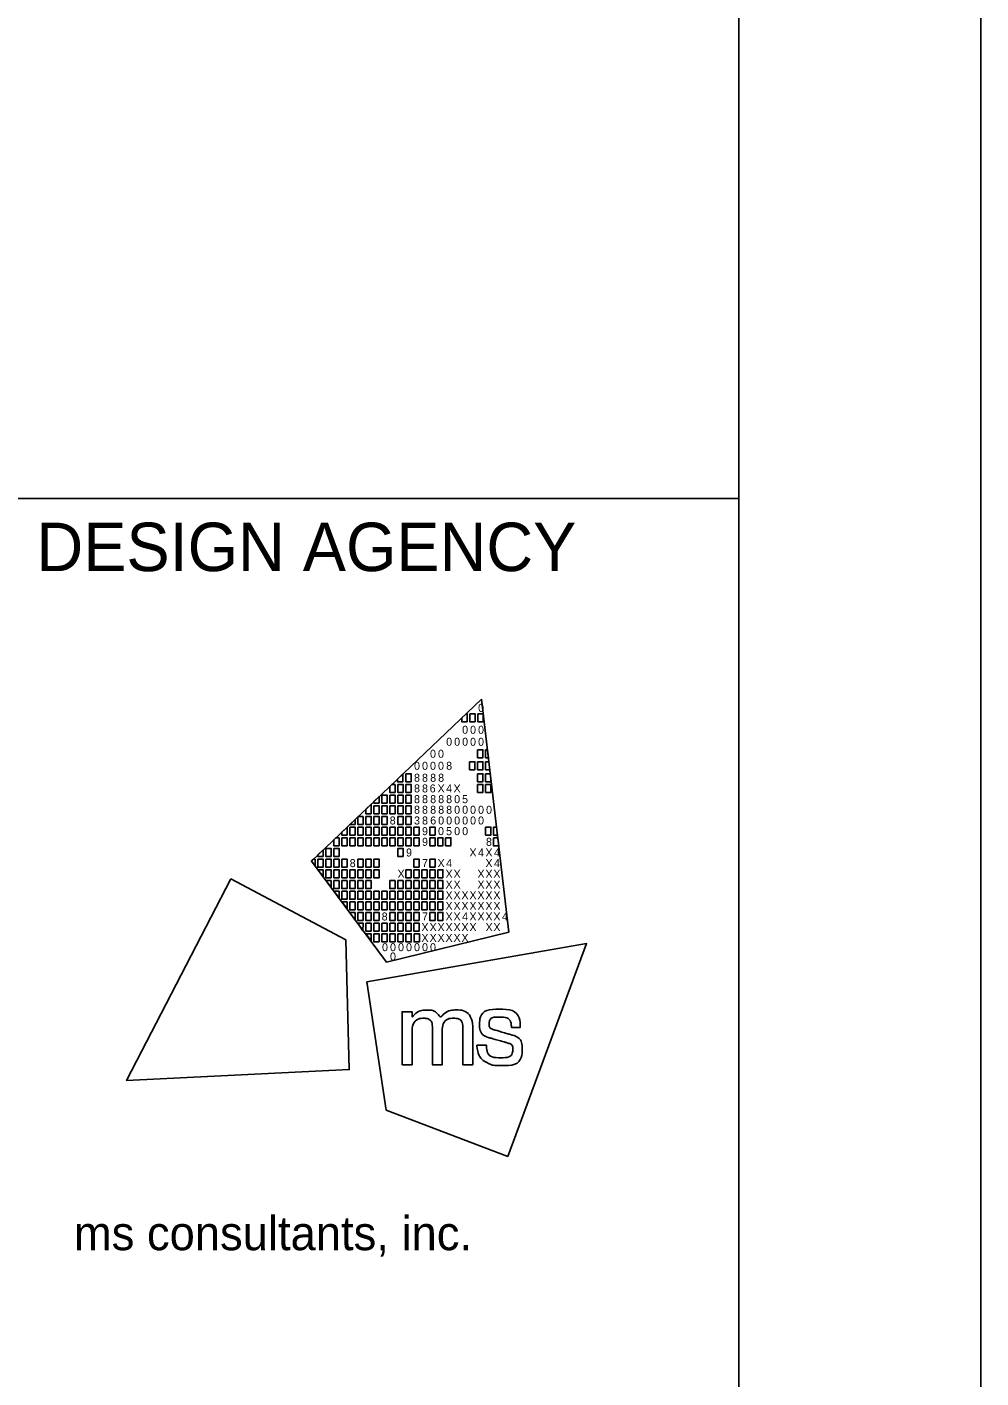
# Model space of a CAD drawing. Extents: x 0 to 34, y 0 to 22.
# Drawn here: x 32.03 to 34, y 2.685 to 5.473 of the extents above; entities that cross this region are included whole.
import ezdxf

# ---------------------------------------------------------------- set-up
doc = ezdxf.new("R2010")
doc.units = 0
for name, color, linetype in [('SH_Border', 7, 'Continuous'), ('SH_Cut_Line', 7, 'Continuous'), ('SH_Data', 7, 'Continuous'), ('SH_Text', 7, 'Continuous')]:
    doc.layers.add(name, color=color, linetype=linetype)

msp = doc.modelspace()

# ---------------------------------------------------------------- linework, layer by layer
at = {"layer": 'SH_Border'}
msp.add_line((32, 4.5), (33.5, 4.5), dxfattribs=at)
msp.add_lwpolyline([(1.5, 21.5), (33.5, 21.5), (33.5, 0.5), (1.5, 0.5)], close=True, dxfattribs=at)
at = {"layer": 'SH_Cut_Line'}
msp.add_lwpolyline([(0, 0), (34, 0), (34, 22), (0, 22)], close=True, dxfattribs=at)
at = {"layer": 'SH_Data'}
msp.add_line((32.75, 3.5), (32.75, 3.5), dxfattribs=at)
at = {"layer": 'SH_Text'}
for p, q in [((32.6175, 3.7519), (32.9688, 4.0861)), ((32.9688, 4.0861), (32.9688, 4.0861)), ((32.9688, 4.0861), (33.0253, 3.6052)), ((32.773, 3.543), (32.6175, 3.7519)), ((33.0253, 3.6052), (32.773, 3.543))]:
    msp.add_line(p, q, dxfattribs=at)
for points in [[(32.9279, 4.0472), (32.9369, 4.0558), (32.9389, 4.0558), (32.9389, 4.0393), (32.9279, 4.0393)], [(32.9444, 4.0558), (32.9554, 4.0558), (32.9554, 4.0393), (32.9444, 4.0393)], [(32.9609, 4.0558), (32.9719, 4.0558), (32.9719, 4.0393), (32.9609, 4.0393)], [(32.9606, 3.9815), (32.9716, 3.9815), (32.9716, 3.965), (32.9606, 3.965)], [(32.9771, 3.9815), (32.9811, 3.9815), (32.983, 3.965), (32.9771, 3.965)], [(32.7953, 3.9211), (32.8064, 3.9316), (32.8064, 3.9154), (32.7953, 3.9154)], [(32.8123, 3.9319), (32.8233, 3.9319), (32.8233, 3.9154), (32.8123, 3.9154)], [(32.9441, 3.9567), (32.9551, 3.9567), (32.9551, 3.9402), (32.9441, 3.9402)], [(32.9606, 3.9567), (32.9716, 3.9567), (32.9716, 3.9402), (32.9606, 3.9402)], [(32.9606, 3.9319), (32.9716, 3.9319), (32.9716, 3.9154), (32.9606, 3.9154)], [(32.9771, 3.9567), (32.984, 3.9567), (32.9859, 3.9402), (32.9771, 3.9402)], [(32.9771, 3.9319), (32.9869, 3.9319), (32.9881, 3.9218), (32.9881, 3.9154), (32.9771, 3.9154)], [(32.7958, 3.9099), (32.8068, 3.9099), (32.8068, 3.8934), (32.7958, 3.8934)], [(32.8123, 3.9099), (32.8233, 3.9099), (32.8233, 3.8934), (32.8123, 3.8934)], [(32.9606, 3.9099), (32.9716, 3.9099), (32.9716, 3.8934), (32.9606, 3.8934)], [(32.9771, 3.9099), (32.9881, 3.9099), (32.9881, 3.8934), (32.9771, 3.8934)], [(32.7627, 3.8879), (32.7737, 3.8879), (32.7737, 3.8714), (32.7627, 3.8714)], [(32.7793, 3.8879), (32.7903, 3.8879), (32.7903, 3.8714), (32.7793, 3.8714)], [(32.7958, 3.8879), (32.8068, 3.8879), (32.8068, 3.8714), (32.7958, 3.8714)], [(32.8123, 3.8879), (32.8233, 3.8879), (32.8233, 3.8714), (32.8123, 3.8714)], [(32.7462, 3.8659), (32.7572, 3.8659), (32.7572, 3.8494), (32.7462, 3.8494)], [(32.7627, 3.8659), (32.7737, 3.8659), (32.7737, 3.8494), (32.7627, 3.8494)], [(32.7793, 3.8659), (32.7903, 3.8659), (32.7903, 3.8494), (32.7793, 3.8494)], [(32.7958, 3.8659), (32.8068, 3.8659), (32.8068, 3.8494), (32.7958, 3.8494)], [(32.8123, 3.8659), (32.8233, 3.8659), (32.8233, 3.8494), (32.8123, 3.8494)], [(32.6967, 3.8218), (32.7077, 3.8218), (32.7077, 3.8053), (32.6967, 3.8053)], [(32.7132, 3.8218), (32.7242, 3.8218), (32.7242, 3.8053), (32.7132, 3.8053)], [(32.7297, 3.8439), (32.7407, 3.8439), (32.7407, 3.8273), (32.7297, 3.8273)], [(32.7297, 3.8218), (32.7407, 3.8218), (32.7407, 3.8053), (32.7297, 3.8053)], [(32.7462, 3.8439), (32.7572, 3.8439), (32.7572, 3.8273), (32.7462, 3.8273)], [(32.7462, 3.8218), (32.7572, 3.8218), (32.7572, 3.8053), (32.7462, 3.8053)], [(32.7627, 3.8439), (32.7737, 3.8439), (32.7737, 3.8273), (32.7627, 3.8273)], [(32.7627, 3.8218), (32.7737, 3.8218), (32.7737, 3.8053), (32.7627, 3.8053)], [(32.7793, 3.8218), (32.7903, 3.8218), (32.7903, 3.8053), (32.7793, 3.8053)], [(32.7958, 3.8439), (32.8068, 3.8439), (32.8068, 3.8273), (32.7958, 3.8273)], [(32.7958, 3.8218), (32.8068, 3.8218), (32.8068, 3.8053), (32.7958, 3.8053)], [(32.8123, 3.8439), (32.8233, 3.8439), (32.8233, 3.8273), (32.8123, 3.8273)], [(32.8123, 3.8218), (32.8233, 3.8218), (32.8233, 3.8053), (32.8123, 3.8053)], [(32.8288, 3.8218), (32.8398, 3.8218), (32.8398, 3.8053), (32.8288, 3.8053)], [(32.8618, 3.8218), (32.8728, 3.8218), (32.8728, 3.8053), (32.8618, 3.8053)], [(32.9771, 3.8218), (32.9881, 3.8218), (32.9881, 3.8053), (32.9771, 3.8053)], [(32.9935, 3.8218), (32.9998, 3.8218), (33.0018, 3.8053), (32.9935, 3.8053)], [(32.6802, 3.7998), (32.6912, 3.7998), (32.6912, 3.7833), (32.6802, 3.7833)], [(32.6967, 3.7998), (32.7077, 3.7998), (32.7077, 3.7833), (32.6967, 3.7833)], [(32.7132, 3.7998), (32.7242, 3.7998), (32.7242, 3.7833), (32.7132, 3.7833)], [(32.7297, 3.7998), (32.7407, 3.7998), (32.7407, 3.7833), (32.7297, 3.7833)], [(32.7462, 3.7998), (32.7572, 3.7998), (32.7572, 3.7833), (32.7462, 3.7833)], [(32.7627, 3.7998), (32.7737, 3.7998), (32.7737, 3.7833), (32.7627, 3.7833)], [(32.7793, 3.7998), (32.7903, 3.7998), (32.7903, 3.7833), (32.7793, 3.7833)], [(32.7958, 3.7998), (32.8068, 3.7998), (32.8068, 3.7833), (32.7958, 3.7833)], [(32.8123, 3.7998), (32.8233, 3.7998), (32.8233, 3.7833), (32.8123, 3.7833)], [(32.8288, 3.7998), (32.8398, 3.7998), (32.8398, 3.7833), (32.8288, 3.7833)], [(32.8618, 3.7998), (32.8728, 3.7998), (32.8728, 3.7833), (32.8618, 3.7833)], [(32.8783, 3.7998), (32.8893, 3.7998), (32.8893, 3.7833), (32.8783, 3.7833)], [(32.8947, 3.7998), (32.9057, 3.7998), (32.9057, 3.7833), (32.8947, 3.7833)], [(32.9935, 3.7998), (33.0024, 3.7998), (33.0044, 3.7833), (32.9935, 3.7833)], [(32.6471, 3.7778), (32.6581, 3.7778), (32.6581, 3.7613), (32.6471, 3.7613)], [(32.6637, 3.7778), (32.6747, 3.7778), (32.6747, 3.7613), (32.6637, 3.7613)], [(32.7958, 3.7778), (32.8068, 3.7778), (32.8068, 3.7613), (32.7958, 3.7613)], [(32.6306, 3.7558), (32.6416, 3.7558), (32.6416, 3.7393), (32.6306, 3.7393)], [(32.6471, 3.7558), (32.6581, 3.7558), (32.6581, 3.7393), (32.6471, 3.7393)], [(32.6637, 3.7558), (32.6747, 3.7558), (32.6747, 3.7393), (32.6637, 3.7393)], [(32.6802, 3.7558), (32.6912, 3.7558), (32.6912, 3.7393), (32.6802, 3.7393)], [(32.7132, 3.7558), (32.7242, 3.7558), (32.7242, 3.7393), (32.7132, 3.7393)], [(32.7297, 3.7558), (32.7407, 3.7558), (32.7407, 3.7393), (32.7297, 3.7393)], [(32.7462, 3.7558), (32.7572, 3.7558), (32.7572, 3.7393), (32.7462, 3.7393)], [(32.8288, 3.7558), (32.8398, 3.7558), (32.8398, 3.7393), (32.8288, 3.7393)], [(32.8618, 3.7558), (32.8728, 3.7558), (32.8728, 3.7393), (32.8618, 3.7393)], [(32.6306, 3.7338), (32.6416, 3.7338), (32.6416, 3.72)], [(32.6471, 3.7338), (32.6581, 3.7338), (32.6581, 3.7173), (32.6471, 3.7173)], [(32.6471, 3.7117), (32.6581, 3.7117), (32.6581, 3.698)], [(32.6637, 3.7338), (32.6747, 3.7338), (32.6747, 3.7173), (32.6637, 3.7173)], [(32.6637, 3.7117), (32.6747, 3.7117), (32.6747, 3.6952), (32.6637, 3.6952)], [(32.6802, 3.7338), (32.6912, 3.7338), (32.6912, 3.7173), (32.6802, 3.7173)], [(32.6802, 3.7117), (32.6912, 3.7117), (32.6912, 3.6952), (32.6802, 3.6952)], [(32.6967, 3.7338), (32.7077, 3.7338), (32.7077, 3.7173), (32.6967, 3.7173)], [(32.6967, 3.7117), (32.7077, 3.7117), (32.7077, 3.6952), (32.6967, 3.6952)], [(32.7132, 3.7338), (32.7242, 3.7338), (32.7242, 3.7173), (32.7132, 3.7173)], [(32.7132, 3.7117), (32.7242, 3.7117), (32.7242, 3.6952), (32.7132, 3.6952)], [(32.7297, 3.7338), (32.7407, 3.7338), (32.7407, 3.7173), (32.7297, 3.7173)], [(32.7297, 3.7117), (32.7407, 3.7117), (32.7407, 3.6952), (32.7297, 3.6952)], [(32.7462, 3.7338), (32.7572, 3.7338), (32.7572, 3.7173), (32.7462, 3.7173)], [(32.7793, 3.7117), (32.7903, 3.7117), (32.7903, 3.6952), (32.7793, 3.6952)], [(32.7958, 3.7117), (32.8068, 3.7117), (32.8068, 3.6952), (32.7958, 3.6952)], [(32.8123, 3.7338), (32.8233, 3.7338), (32.8233, 3.7173), (32.8123, 3.7173)], [(32.8123, 3.7117), (32.8233, 3.7117), (32.8233, 3.6952), (32.8123, 3.6952)], [(32.8288, 3.7338), (32.8398, 3.7338), (32.8398, 3.7173), (32.8288, 3.7173)], [(32.8288, 3.7117), (32.8398, 3.7117), (32.8398, 3.6952), (32.8288, 3.6952)], [(32.8453, 3.7338), (32.8563, 3.7338), (32.8563, 3.7173), (32.8453, 3.7173)], [(32.8453, 3.7117), (32.8563, 3.7117), (32.8563, 3.6952), (32.8453, 3.6952)], [(32.8618, 3.7338), (32.8728, 3.7338), (32.8728, 3.7173), (32.8618, 3.7173)], [(32.8618, 3.7117), (32.8728, 3.7117), (32.8728, 3.6952), (32.8618, 3.6952)], [(32.8783, 3.7338), (32.8893, 3.7338), (32.8893, 3.7173), (32.8783, 3.7173)], [(32.8783, 3.7117), (32.8893, 3.7117), (32.8893, 3.6952), (32.8783, 3.6952)], [(32.6637, 3.6897), (32.6747, 3.6897), (32.6747, 3.676)], [(32.6747, 3.6897), (32.6747, 3.6897), (32.6747, 3.6897)], [(32.6802, 3.6897), (32.6912, 3.6897), (32.6912, 3.6732), (32.6802, 3.6732)], [(32.6967, 3.6897), (32.7077, 3.6897), (32.7077, 3.6732), (32.6967, 3.6732)], [(32.7132, 3.6897), (32.7242, 3.6897), (32.7242, 3.6732), (32.7132, 3.6732)], [(32.7297, 3.6897), (32.7407, 3.6897), (32.7407, 3.6732), (32.7297, 3.6732)], [(32.7462, 3.6897), (32.7572, 3.6897), (32.7572, 3.6732), (32.7462, 3.6732)], [(32.7627, 3.6897), (32.7737, 3.6897), (32.7737, 3.6732), (32.7627, 3.6732)], [(32.7793, 3.6897), (32.7903, 3.6897), (32.7903, 3.6732), (32.7793, 3.6732)], [(32.7958, 3.6897), (32.8068, 3.6897), (32.8068, 3.6732), (32.7958, 3.6732)], [(32.8123, 3.6897), (32.8233, 3.6897), (32.8233, 3.6732), (32.8123, 3.6732)], [(32.8288, 3.6897), (32.8398, 3.6897), (32.8398, 3.6732), (32.8288, 3.6732)], [(32.8453, 3.6897), (32.8563, 3.6897), (32.8563, 3.6732), (32.8453, 3.6732)], [(32.8618, 3.6897), (32.8728, 3.6897), (32.8728, 3.6732), (32.8618, 3.6732)], [(32.8783, 3.6897), (32.8893, 3.6897), (32.8893, 3.6732), (32.8783, 3.6732)], [(32.6802, 3.6677), (32.6912, 3.6677), (32.6912, 3.654)], [(32.6967, 3.6677), (32.7077, 3.6677), (32.7077, 3.6512), (32.6967, 3.6512)], [(32.7132, 3.6677), (32.7242, 3.6677), (32.7242, 3.6512), (32.7132, 3.6512)], [(32.7297, 3.6677), (32.7407, 3.6677), (32.7407, 3.6512), (32.7297, 3.6512)], [(32.7462, 3.6677), (32.7572, 3.6677), (32.7572, 3.6512), (32.7462, 3.6512)], [(32.7627, 3.6677), (32.7737, 3.6677), (32.7737, 3.6512), (32.7627, 3.6512)], [(32.7793, 3.6677), (32.7903, 3.6677), (32.7903, 3.6512), (32.7793, 3.6512)], [(32.7958, 3.6677), (32.8068, 3.6677), (32.8068, 3.6512), (32.7958, 3.6512)], [(32.8123, 3.6677), (32.8233, 3.6677), (32.8233, 3.6512), (32.8123, 3.6512)], [(32.8288, 3.6677), (32.8398, 3.6677), (32.8398, 3.6512), (32.8288, 3.6512)], [(32.8453, 3.6677), (32.8563, 3.6677), (32.8563, 3.6512), (32.8453, 3.6512)], [(32.8618, 3.6677), (32.8728, 3.6677), (32.8728, 3.6512), (32.8618, 3.6512)], [(32.8783, 3.6677), (32.8893, 3.6677), (32.8893, 3.6512), (32.8783, 3.6512)], [(32.7077, 3.6305), (32.6965, 3.6457), (32.7077, 3.6457)], [(32.7132, 3.6457), (32.7242, 3.6457), (32.7242, 3.6292), (32.7132, 3.6292)], [(32.724, 3.6082), (32.7132, 3.6237), (32.7242, 3.6237)], [(32.7297, 3.6457), (32.7407, 3.6457), (32.7407, 3.6292), (32.7297, 3.6292)], [(32.7462, 3.6457), (32.7572, 3.6457), (32.7572, 3.6292), (32.7462, 3.6292)], [(32.7793, 3.6457), (32.7903, 3.6457), (32.7903, 3.6292), (32.7793, 3.6292)], [(32.7958, 3.6457), (32.8068, 3.6457), (32.8068, 3.6292), (32.7958, 3.6292)], [(32.8123, 3.6457), (32.8233, 3.6457), (32.8233, 3.6292), (32.8123, 3.6292)], [(32.8288, 3.6457), (32.8398, 3.6457), (32.8398, 3.6292), (32.8288, 3.6292)], [(32.8618, 3.6457), (32.8728, 3.6457), (32.8728, 3.6292), (32.8618, 3.6292)], [(32.8783, 3.6457), (32.8893, 3.6457), (32.8893, 3.6292), (32.8783, 3.6292)], [(32.7297, 3.6237), (32.7407, 3.6237), (32.7407, 3.6072), (32.7297, 3.6072)], [(32.7302, 3.6017), (32.7407, 3.6017), (32.7408, 3.5875)], [(32.7462, 3.6237), (32.7572, 3.6237), (32.7572, 3.6072), (32.7462, 3.6072)], [(32.7463, 3.6017), (32.7573, 3.6017), (32.7573, 3.5852), (32.7463, 3.5852)], [(32.7627, 3.6237), (32.7737, 3.6237), (32.7737, 3.6072), (32.7627, 3.6072)], [(32.763, 3.6017), (32.774, 3.6017), (32.774, 3.5852), (32.763, 3.5852)], [(32.7793, 3.6237), (32.7903, 3.6237), (32.7903, 3.6072), (32.7793, 3.6072)], [(32.7794, 3.6017), (32.7904, 3.6017), (32.7904, 3.5852), (32.7794, 3.5852)], [(32.7958, 3.6237), (32.8068, 3.6237), (32.8068, 3.6072), (32.7958, 3.6072)], [(32.796, 3.6017), (32.807, 3.6017), (32.807, 3.5852), (32.796, 3.5852)], [(32.8123, 3.6237), (32.8233, 3.6237), (32.8233, 3.6072), (32.8123, 3.6072)], [(32.8129, 3.6017), (32.8239, 3.6017), (32.8239, 3.5851), (32.8129, 3.5851)], [(32.8288, 3.6237), (32.8398, 3.6237), (32.8398, 3.6072), (32.8288, 3.6072)], [(32.8296, 3.6017), (32.8406, 3.6017), (32.8406, 3.5851), (32.8296, 3.5851)]]:
    msp.add_lwpolyline(points, close=True, dxfattribs=at)
for points in [[(32.7903, 3.9099), (32.7836, 3.9099), (32.7793, 3.9058), (32.7793, 3.8934), (32.7903, 3.8934), (32.7903, 3.9099)], [(32.7572, 3.8849), (32.7462, 3.8744), (32.7462, 3.8714), (32.7572, 3.8714), (32.7572, 3.8849)], [(32.7407, 3.8691), (32.7297, 3.8587), (32.7297, 3.8494), (32.7407, 3.8494), (32.7407, 3.8691)], [(32.6912, 3.822), (32.6802, 3.8115), (32.6802, 3.8053), (32.6912, 3.8053), (32.6912, 3.822)], [(32.7077, 3.8377), (32.6968, 3.8273), (32.7077, 3.8273), (32.7077, 3.8377)], [(32.7242, 3.8439), (32.7141, 3.8439), (32.7132, 3.843), (32.7132, 3.8273), (32.7242, 3.8273), (32.7242, 3.8439)], [(32.6747, 3.7998), (32.6679, 3.7998), (32.6637, 3.7958), (32.6637, 3.7833), (32.6747, 3.7833), (32.6747, 3.7998)], [(32.6416, 3.7749), (32.6306, 3.7644), (32.6306, 3.7613), (32.6416, 3.7613), (32.6416, 3.7749)], [(32.6251, 3.7558), (32.6216, 3.7558), (32.6175, 3.7519), (32.6251, 3.7417), (32.6251, 3.7558)], [(32.4512, 3.7149), (32.2359, 3.2988), (32.6956, 3.3215), (32.6884, 3.5892), (32.4512, 3.7149)], [(33.0229, 3.1422), (33.1859, 3.5814), (32.7324, 3.5029), (32.7722, 3.2381), (33.0229, 3.1422)]]:
    msp.add_lwpolyline(points, dxfattribs=at)
for points in [[(32.8048, 3.3315), (32.8048, 3.3315), (32.8048, 3.4409), (32.8048, 3.4409), (32.8048, 3.4409), (32.8255, 3.4409), (32.8255, 3.4409), (32.8255, 3.4409), (32.8255, 3.4297), (32.8255, 3.4297), (32.8346, 3.4399), (32.8457, 3.4445), (32.8555, 3.4445), (32.8688, 3.4445), (32.8791, 3.4372), (32.8837, 3.4266), (32.8915, 3.4381), (32.905, 3.4446), (32.9166, 3.4446), (32.9325, 3.4446), (32.9451, 3.435), (32.9494, 3.4213), (32.9494, 3.4212), (32.9494, 3.4212), (32.9494, 3.4212), (32.9501, 3.419), (32.9506, 3.4172), (32.9506, 3.4071), (32.9506, 3.4071), (32.9506, 3.3314), (32.9506, 3.3314), (32.9506, 3.3314), (32.9303, 3.3314), (32.9303, 3.3314), (32.9303, 3.3314), (32.9303, 3.4048), (32.9303, 3.4048), (32.9303, 3.4201), (32.9219, 3.4274), (32.911, 3.4274), (32.8995, 3.4274), (32.8879, 3.4171), (32.8879, 3.4001), (32.8879, 3.4001), (32.8879, 3.3315), (32.8879, 3.3315), (32.8879, 3.3315), (32.8674, 3.3315), (32.8674, 3.3315), (32.8674, 3.3315), (32.8674, 3.4059), (32.8674, 3.4059), (32.8674, 3.4203), (32.8588, 3.4274), (32.8496, 3.4274), (32.8384, 3.4274), (32.8254, 3.417), (32.8254, 3.3962), (32.8254, 3.3962), (32.8254, 3.3315), (32.8254, 3.3315), (32.8254, 3.3315), (32.8048, 3.3315), (32.8048, 3.3315)], [(32.9595, 3.3709), (32.9595, 3.3709), (32.9595, 3.3717), (32.9595, 3.3717), (32.9595, 3.3717), (32.9603, 3.3717), (32.9603, 3.3717), (32.9603, 3.3717), (32.9783, 3.3717), (32.9783, 3.3717), (32.9783, 3.3717), (32.9789, 3.3717), (32.9789, 3.3717), (32.9789, 3.3717), (32.979, 3.371), (32.979, 3.371), (32.9803, 3.3554), (32.9887, 3.346), (33.009, 3.346), (33.0273, 3.346), (33.0333, 3.3554), (33.0333, 3.3631), (33.0333, 3.3732), (33.0256, 3.3758), (33.0175, 3.378), (33.0175, 3.378), (32.987, 3.3867), (32.987, 3.3867), (32.972, 3.3909), (32.9648, 3.4019), (32.9648, 3.4142), (32.9648, 3.4303), (32.9768, 3.4462), (33.0052, 3.4462), (33.0348, 3.4462), (33.0489, 3.4285), (33.0489, 3.4095), (33.0489, 3.4095), (33.0489, 3.4087), (33.0489, 3.4087), (33.0489, 3.4087), (33.0482, 3.4087), (33.0482, 3.4087), (33.0482, 3.4087), (33.0312, 3.4087), (33.0312, 3.4087), (33.0312, 3.4087), (33.0305, 3.4087), (33.0305, 3.4087), (33.0305, 3.4087), (33.0305, 3.4094), (33.0305, 3.4094), (33.0301, 3.4208), (33.0226, 3.43), (33.0056, 3.43), (32.9891, 3.43), (32.9843, 3.4218), (32.9843, 3.4157), (32.9843, 3.4108), (32.9869, 3.4059), (32.9959, 3.4033), (32.9959, 3.4033), (33.0255, 3.3948), (33.0255, 3.3948), (33.0462, 3.3889), (33.0527, 3.3777), (33.0527, 3.3639), (33.0527, 3.3462), (33.041, 3.3298), (33.0087, 3.3298), (32.9952, 3.3298), (32.9877, 3.3321), (32.9823, 3.3348), (32.969, 3.3414), (32.9609, 3.3536), (32.9595, 3.3709)]]:
    msp.add_open_spline(points, degree=3, dxfattribs=at)

# ---------------------------------------------------------------- texts
at = {"layer": 'SH_Border'}
msp.add_text('ms consultants, inc.', height=0.07, rotation=360, dxfattribs=at).set_placement((32.1273, 2.9489))
at = {"layer": 'SH_Data'}
msp.add_text('DESIGN AGENCY', height=0.1, dxfattribs=at).set_placement((32.05, 4.35))
at = {"layer": 'SH_Text'}
for s, p in [('0', (32.9617, 4.0597)), ('0', (32.9288, 4.0145)), ('0', (32.9452, 4.0145)), ('0', (32.9617, 4.0145)), ('0', (32.8958, 3.9897)), ('0', (32.9123, 3.9897)), ('0', (32.9288, 3.9897)), ('0', (32.9452, 3.9897)), ('0', (32.9617, 3.9897)), ('0', (32.8625, 3.965)), ('0', (32.879, 3.965)), ('0', (32.8295, 3.9402)), ('8', (32.8295, 3.9154)), ('0', (32.846, 3.9402)), ('8', (32.846, 3.9154)), ('0', (32.8625, 3.9402)), ('8', (32.8628, 3.9154)), ('0', (32.879, 3.9402)), ('8', (32.8793, 3.9154)), ('8', (32.8958, 3.9402)), ('8', (32.8295, 3.8934)), ('8', (32.846, 3.8934)), ('6', (32.8618, 3.8934)), ('X', (32.8781, 3.8934)), ('4', (32.8958, 3.8934)), ('X', (32.911, 3.8934)), ('8', (32.8295, 3.8713)), ('8', (32.846, 3.8713)), ('8', (32.8628, 3.8713)), ('8', (32.8794, 3.8713)), ('8', (32.8958, 3.8713)), ('0', (32.9123, 3.8713)), ('5', (32.9287, 3.8713)), ('8', (32.8295, 3.8494)), ('8', (32.846, 3.8494)), ('8', (32.8628, 3.8494)), ('8', (32.8794, 3.8494)), ('8', (32.8958, 3.8494)), ('0', (32.9123, 3.8494)), ('0', (32.9288, 3.8494)), ('0', (32.9452, 3.8494)), ('0', (32.9617, 3.8494)), ('0', (32.9782, 3.8494)), ('8', (32.7793, 3.8273)), ('3', (32.8295, 3.8273)), ('8', (32.846, 3.8273)), ('9', (32.846, 3.8053)), ('6', (32.8629, 3.8273)), ('0', (32.879, 3.8053)), ('0', (32.8793, 3.8273)), ('5', (32.8957, 3.8053)), ('0', (32.8958, 3.8273)), ('0', (32.9123, 3.8273)), ('0', (32.9123, 3.8053)), ('0', (32.9288, 3.8273)), ('0', (32.9288, 3.8053)), ('0', (32.9452, 3.8273)), ('0', (32.9617, 3.8273)), ('9', (32.846, 3.7833)), ('8', (32.9781, 3.7833)), ('9', (32.813, 3.7613)), ('X', (32.9439, 3.7613)), ('4', (32.9617, 3.7613)), ('X', (32.9769, 3.7613)), ('4', (32.9946, 3.7613)), ('8', (32.6967, 3.7393)), ('7', (32.846, 3.7393)), ('X', (32.8781, 3.7393)), ('4', (32.8958, 3.7393)), ('X', (32.9769, 3.7393)), ('4', (32.9946, 3.7393)), ('X', (32.7955, 3.7173)), ('X', (32.8945, 3.7173)), ('X', (32.8945, 3.6952)), ('X', (32.911, 3.7173)), ('X', (32.911, 3.6952)), ('X', (32.9604, 3.7173)), ('X', (32.9604, 3.6952)), ('X', (32.9769, 3.7173)), ('X', (32.9769, 3.6952)), ('X', (32.9933, 3.7173)), ('X', (32.9933, 3.6952)), ('X', (32.8945, 3.6732)), ('X', (32.911, 3.6732)), ('X', (32.9274, 3.6732)), ('X', (32.9439, 3.6732)), ('X', (32.9604, 3.6732)), ('X', (32.9769, 3.6732)), ('X', (32.9933, 3.6732)), ('X', (32.8945, 3.6512)), ('X', (32.911, 3.6512)), ('X', (32.9274, 3.6512)), ('X', (32.9439, 3.6512)), ('X', (32.9604, 3.6512)), ('X', (32.9769, 3.6512)), ('X', (32.9933, 3.6512)), ('8', (32.7627, 3.6292)), ('7', (32.846, 3.6292)), ('X', (32.8945, 3.6292)), ('X', (32.911, 3.6292)), ('4', (32.9288, 3.6292)), ('X', (32.9439, 3.6292)), ('X', (32.9604, 3.6292)), ('X', (32.9769, 3.6292)), ('X', (32.9933, 3.6292)), ('4', (33.0111, 3.6292)), ('X', (32.8447, 3.6072)), ('X', (32.8447, 3.5851)), ('X', (32.8616, 3.6072)), ('X', (32.8616, 3.5851)), ('X', (32.878, 3.6072)), ('X', (32.878, 3.5851)), ('X', (32.8945, 3.6072)), ('X', (32.8945, 3.5851)), ('X', (32.911, 3.6072)), ('X', (32.911, 3.5851)), ('X', (32.9274, 3.6072)), ('X', (32.9274, 3.5851)), ('X', (32.9439, 3.6072)), ('X', (32.9771, 3.6072)), ('X', (32.9933, 3.6072)), ('0', (32.7634, 3.5659)), ('0', (32.7799, 3.5659)), ('0', (32.7965, 3.5659)), ('0', (32.813, 3.5659)), ('0', (32.8295, 3.5659)), ('0', (32.846, 3.5659)), ('0', (32.8625, 3.5659)), ('0', (32.7799, 3.5467))]:
    msp.add_text(s, height=0.0165, rotation=360, dxfattribs=at).set_placement(p)

doc.saveas('drawing.dxf')
